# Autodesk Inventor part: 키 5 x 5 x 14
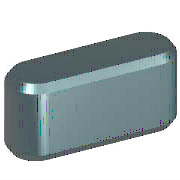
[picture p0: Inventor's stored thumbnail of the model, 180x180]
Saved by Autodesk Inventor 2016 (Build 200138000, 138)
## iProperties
IsCustomPart: 1
Created: 2012-02
Part Number: 키 5 x 5 x 14
Material: 강철, 연강
Description: 키 및 해당 키홈
Document SubType Name: Modeling
Standard: KS B 1311
Designer: mduedu
Standards Organization: KS
Language: ko-KR
Size Designation: 5 x 5 x 14
Categories: <MemberInstance><Categories><Category DisplayName="샤프트 부품" InternalName="7f7aeb1f-a693-4053-b835-cee3144e0d98" Mnemonic="SHFT"><Category DisplayName="키" Interna
Density: 1 g/cm^3
Appearance: 노란색
Author: mduedu
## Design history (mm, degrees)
workplane "Work Plane1"
workplane "Work Plane2"
sketch "스케치1"
  geometry: L1 (2.5, 2.5)-(11.5, 2.5); L2 (11.5, -2.5)-(2.5, -2.5); L3 (0, 9.4)-(0, -7.4) reference; L4 (-5, 0)-(30, 0) reference; L5 (14, 0)-(14, 7); A1 r 2.5 centre (2.5, 0) between (2.5, 2.5) and (2.5, -2.5); A2 r 2.5 centre (11.5, 0) between (11.5, -2.5) and (11.5, 2.5)
  constraints: 6 end point, 5 point on circle, 4 tangent, 3 point on line, 2 centre point, 1 horizontal, 1 parallel, 1 perpendicular
  dimensions: "d0" = 2.5 radius of A1 (= 0.5 x PB); "d13" = 2.5 radius of A2 (= 0.5 x PB); "d14" = 14 distance between parallel lines of L5 L3 (= NLG)
extrude "본체1" new body sketch "스케치1" taper "d3" = 0 deg; stored distance "d4" = 10
workplane "Work Plane3"
body "Solid1"
chamfer "모따기1" distance "d8" = 0.4 (= PHH); stored, may be unused: second distance "d9" = 0.4 (= PHH), angle "d15" = 45 deg
other parameters: "d1" = -3 (= -PNT), "d2" = 2 (= PH - PNT), "NLG" = 14 [user parameter; used in 3 equation terms], "PB" = 5 [user parameter; used in 2 equation terms], "PNT" = 3 [user parameter; used in 2 equation terms], "PH" = 5 [user parameter; used in 1 equation term], "PHH" = 0.4 [user parameter; used in 2 equation terms], "d10" = 0, "d16" = 0, "d17" = 0, "d18" = 0, "WDMIN" = 12 [user parameter], "PLB2" = 14 (= NLG) [user parameter], "WDMAX" = 17 [user parameter], "PLB1" = 14 (= NLG) [user parameter], "RR" = 0.16 [user parameter], "PUEB" = 2.3 [user parameter]
